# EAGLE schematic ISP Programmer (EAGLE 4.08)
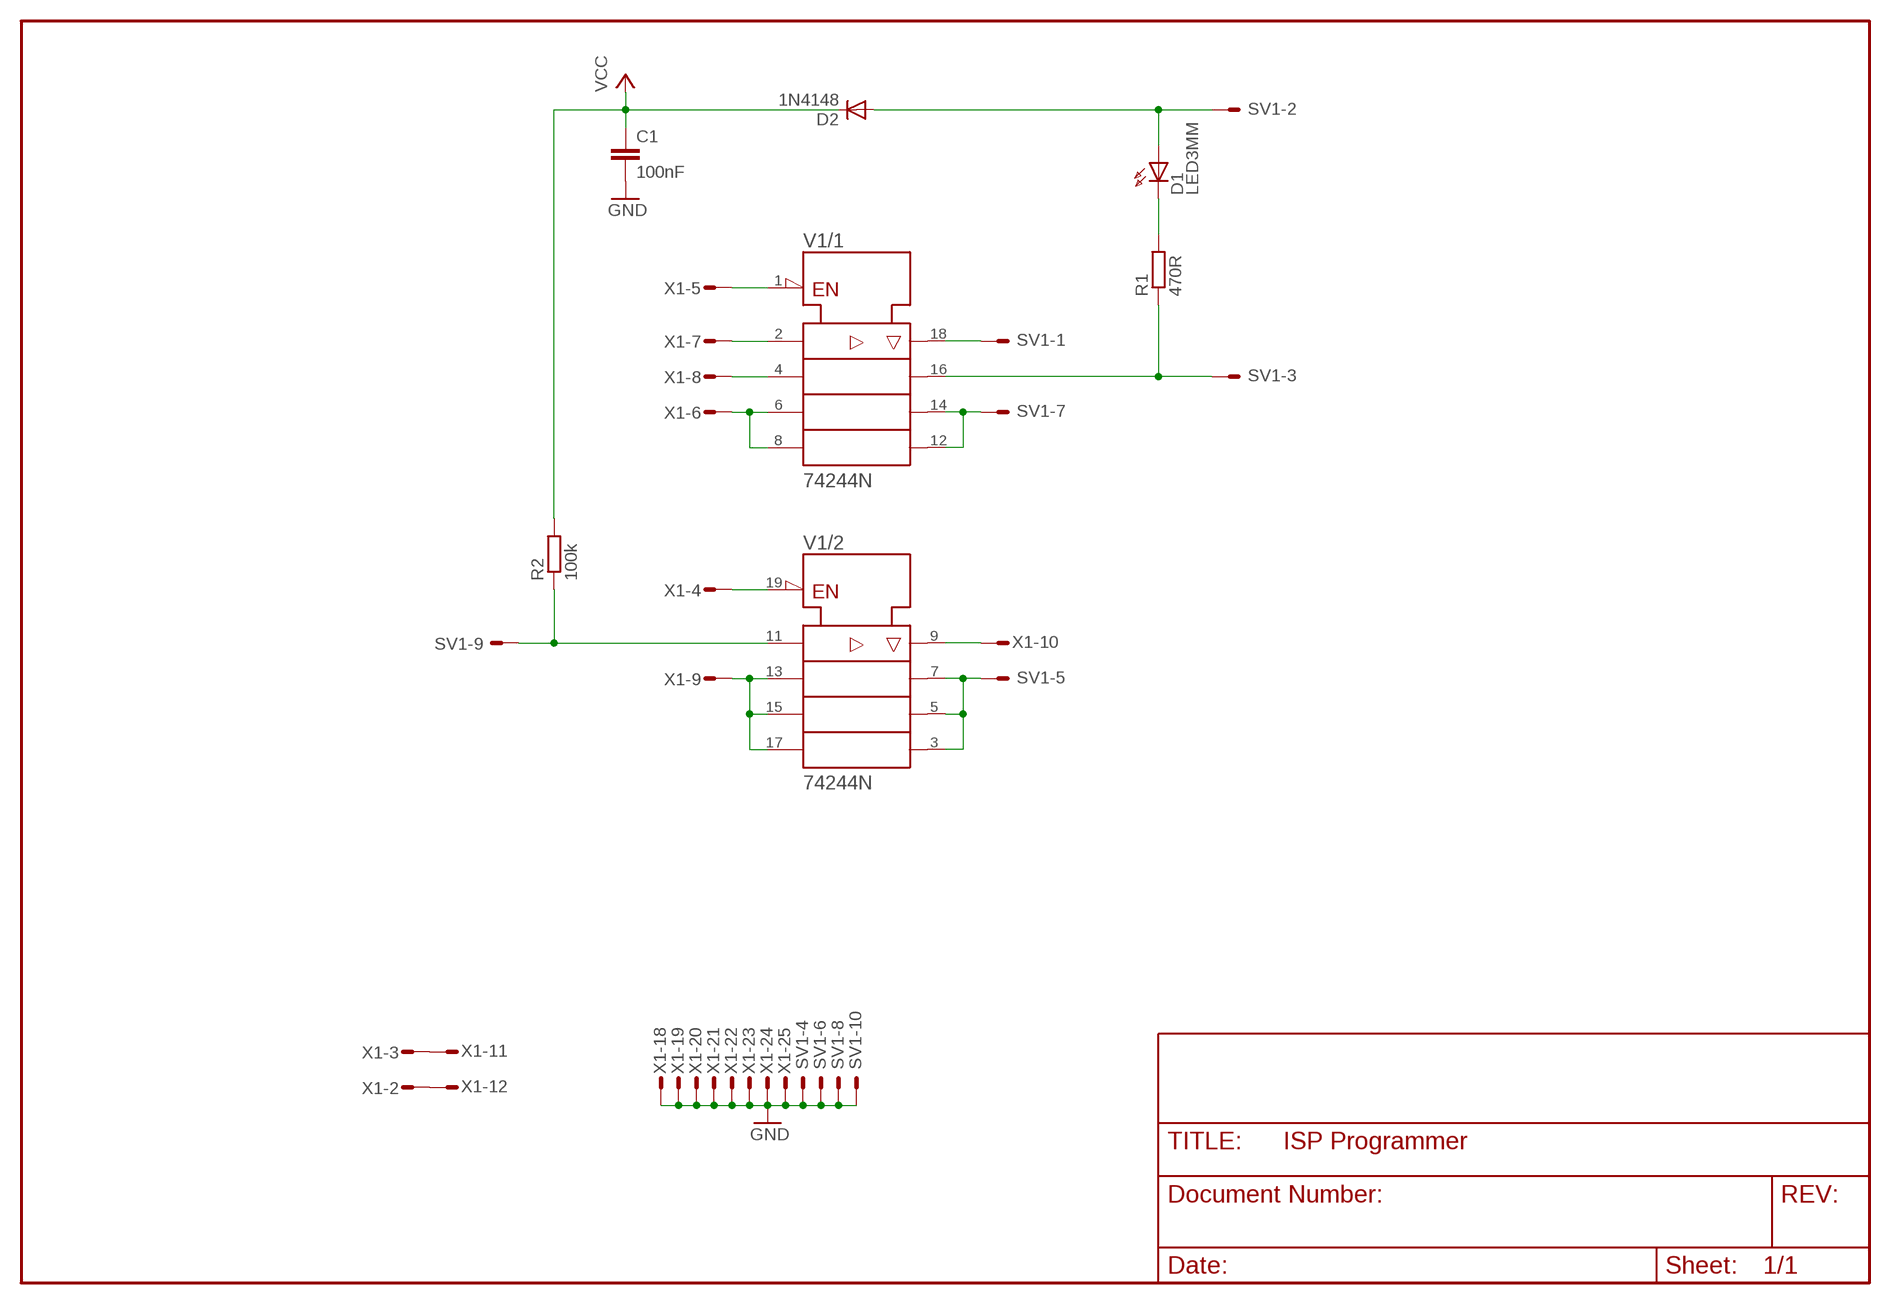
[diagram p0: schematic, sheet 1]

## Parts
C1  100nF  C-EU050-024X044  [C050-024X044]
D1  LED3MM  [LED3MM]
D2  1N4148  [DO35-10]
R1  470R  R-EU_0207/10  [0207/10]
R2  100k  R-EU_0207/10  [0207/10]
SV1  ML10E  [ML10]
V1  74244N  [DIL20]
X1  M25HPS  [M25HP]

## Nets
GND: C1.2
N$1: SV1.1 V1.18(/1:Y1)
N$2: V1.1(/1:G\) X1.5(-5:M)
N$3: V1.2(/1:A1) X1.7(-7:M)
N$4: V1.4(/1:A2) X1.8(-8:M)
N$5: V1.19(/2:G\) X1.4(-4:M)
N$6: V1.6(/1:A3) V1.8(/1:A4) X1.6(-6:M)
N$7: V1.13(/2:A2) V1.15(/2:A3) V1.17(/2:A4) X1.9(-9:M)
N$8: V1.9(/2:Y1) X1.10(-10:M)
N$9: SV1.5 V1.3(/2:Y4) V1.5(/2:Y3) V1.7(/2:Y2)
N$10: R2.1 SV1.9 V1.11(/2:A1)
N$11: SV1.7 V1.12(/1:Y4) V1.14(/1:Y3)
N$12: R1.1 SV1.3 V1.16(/1:Y2)
N$13: D1.K(C) R1.2
N$17: D1.A D2.A SV1.2
N$18: X1.3(-3:M) X1.11(-11:M)
N$19: X1.2(-2:M) X1.12(-12:M)
N$20: SV1.4 SV1.6 SV1.8 SV1.10 X1.18(-18:M) X1.19(-19:M) X1.20(-20:M) X1.21(-21:M) X1.22(-22:M) X1.23(-23:M) X1.24(-24:M) X1.25(-25:M) ; supply symbol labelled GND
VCC: C1.1 D2.C R2.2
Unconnected: X1.1(-1:M) X1.13(-13:M) X1.14(-14:M) X1.15(-15:M) X1.16(-16:M) X1.17(-17:M) X1.G1(-G:G1) X1.G2(-G:G2)

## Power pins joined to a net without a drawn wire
+UB: V1.20(/+UB:+UB)
-UB: V1.10(/-UB:-UB)

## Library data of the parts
C1 = rcl:C-EU: CAPACITOR, European symbol
D1 = led:LED3MM: LED
D2 = diode:1N4148: DIODE
R1 R2 = rcl:R-EU_: RESISTOR, European symbol
SV1 = con-harting-ml:ML10?E: HARTING
V1 = 74ttl-din:74*244: Octal BUFFER and LINE DRIVER, 3-state
X1 = con-subd:M25HPS: SUB-D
